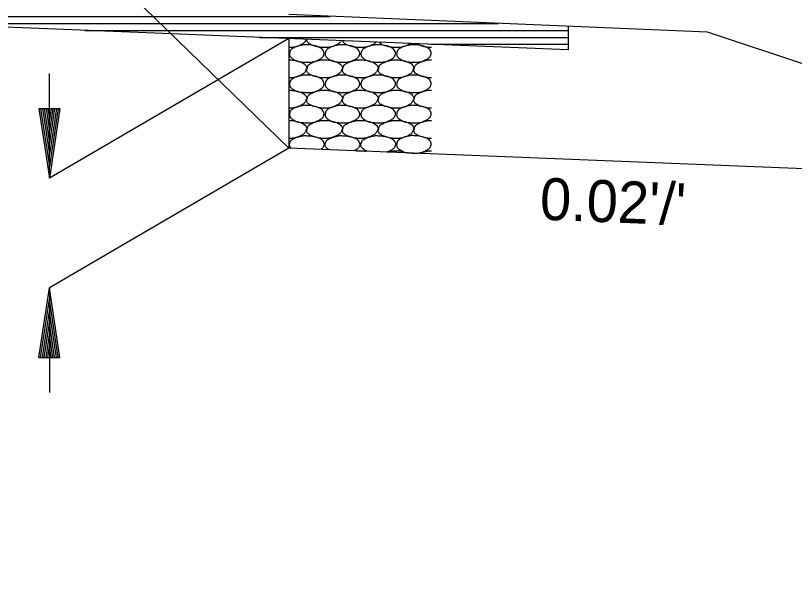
# Model space of a CAD drawing. Extents: x 1955768 to 1955917, y 566446 to 566546.
# Drawn here: x 1955847.75 to 1955858.92, y 566511.42 to 566519.66 of the extents above; entities that cross this region are included whole.
import ezdxf

# ---------------------------------------------------------------- set-up
doc = ezdxf.new("R2010")
doc.units = 0
doc.layers.add('R_Border', color=7, linetype='Continuous')
doc.layers.add('R_Grid', color=7, linetype='Continuous')

msp = doc.modelspace()

# ---------------------------------------------------------------- linework, layer by layer
at = {"layer": 'R_Border'}
for p, q in [((1955851.672, 566517.757), (1955848.84, 566520.502)), ((1955851.759, 566519.325), (1955839.673, 566519.808)), ((1955857.672, 566519.421), (1955851.672, 566519.67)), ((1955843.748, 566519.645), (1955852.265, 566519.645)), ((1955846.248, 566519.545), (1955854.675, 566519.545)), ((1955848.748, 566519.445), (1955855.672, 566519.445)), ((1955855.672, 566519.504), (1955855.672, 566519.164)), ((1955851.248, 566519.345), (1955855.672, 566519.345)), ((1955881.672, 566511.422), (1955857.672, 566519.421)), ((1955851.672, 566519.328), (1955848.238, 566517.328)), ((1955851.672, 566519.328), (1955851.672, 566517.757)), ((1955855.672, 566519.164), (1955851.758, 566519.326)), ((1955853.709, 566519.245), (1955855.672, 566519.245)), ((1955851.672, 566517.757), (1955848.238, 566515.757)), ((1955864.162, 566517.258), (1955851.672, 566517.757))]:
    msp.add_line(p, q, dxfattribs=at)
at = {"layer": 'R_Grid'}
for p, q in [((1955848.238, 566517.328), (1955848.238, 566518.828)), ((1955848.088, 566518.328), (1955848.238, 566517.328)), ((1955848.088, 566518.328), (1955848.388, 566518.328)), ((1955848.113, 566518.328), (1955848.238, 566517.495)), ((1955848.139, 566518.328), (1955848.238, 566517.667)), ((1955848.164, 566518.328), (1955848.238, 566517.834)), ((1955848.19, 566518.328), (1955848.238, 566518.003)), ((1955848.215, 566518.328), (1955848.238, 566518.17)), ((1955848.388, 566518.328), (1955848.238, 566517.328)), ((1955848.287, 566518.328), (1955848.238, 566518.003)), ((1955848.338, 566518.328), (1955848.238, 566517.667)), ((1955848.363, 566518.328), (1955848.238, 566517.495)), ((1955848.313, 566518.328), (1955848.238, 566517.834)), ((1955848.262, 566518.328), (1955848.238, 566518.17)), ((1955848.088, 566514.757), (1955848.238, 566515.757)), ((1955848.238, 566515.757), (1955848.238, 566514.257)), ((1955848.388, 566514.757), (1955848.238, 566515.757)), ((1955848.113, 566514.757), (1955848.238, 566515.59)), ((1955848.363, 566514.757), (1955848.238, 566515.59)), ((1955848.139, 566514.757), (1955848.238, 566515.418)), ((1955848.338, 566514.757), (1955848.238, 566515.418)), ((1955848.164, 566514.757), (1955848.238, 566515.252)), ((1955848.313, 566514.757), (1955848.238, 566515.252)), ((1955848.19, 566514.757), (1955848.238, 566515.082)), ((1955848.287, 566514.757), (1955848.238, 566515.082)), ((1955848.215, 566514.757), (1955848.238, 566514.915)), ((1955848.262, 566514.757), (1955848.238, 566514.915)), ((1955848.088, 566514.757), (1955848.388, 566514.757))]:
    msp.add_line(p, q, dxfattribs=at)
for points in [[(1955851.916, 566519.318), (1955851.914, 566519.3), (1955851.893, 566519.269), (1955851.849, 566519.238), (1955851.79, 566519.213), (1955851.727, 566519.198), (1955851.685, 566519.198), (1955851.672, 566519.198)], [(1955851.928, 566519.238), (1955851.958, 566519.239), (1955852.025, 566519.23), (1955852.118, 566519.204), (1955852.169, 566519.158), (1955852.18, 566519.103), (1955852.156, 566519.059), (1955852.111, 566519.028), (1955852.052, 566519.003), (1955851.987, 566518.987), (1955851.921, 566518.988), (1955851.86, 566518.993), (1955851.791, 566518.998), (1955851.731, 566519.034), (1955851.682, 566519.066), (1955851.677, 566519.117), (1955851.693, 566519.168), (1955851.732, 566519.192), (1955851.78, 566519.213), (1955851.827, 566519.227), (1955851.878, 566519.239), (1955851.91, 566519.24), (1955851.928, 566519.238)], [(1955852.184, 566519.198), (1955852.182, 566519.198), (1955852.157, 566519.198), (1955852.108, 566519.202), (1955852.044, 566519.22), (1955851.979, 566519.238), (1955851.935, 566519.276), (1955851.927, 566519.308), (1955851.926, 566519.318)], [(1955852.422, 566519.298), (1955852.416, 566519.287), (1955852.4, 566519.265), (1955852.361, 566519.238), (1955852.302, 566519.213), (1955852.239, 566519.198), (1955852.197, 566519.198), (1955852.184, 566519.198)], [(1955852.44, 566519.238), (1955852.47, 566519.239), (1955852.537, 566519.23), (1955852.63, 566519.204), (1955852.681, 566519.158), (1955852.692, 566519.103), (1955852.668, 566519.059), (1955852.623, 566519.028), (1955852.564, 566519.003), (1955852.499, 566518.987), (1955852.433, 566518.988), (1955852.372, 566518.993), (1955852.303, 566518.998), (1955852.243, 566519.034), (1955852.194, 566519.066), (1955852.189, 566519.117), (1955852.205, 566519.168), (1955852.244, 566519.192), (1955852.292, 566519.213), (1955852.339, 566519.227), (1955852.39, 566519.239), (1955852.422, 566519.24), (1955852.44, 566519.238)], [(1955852.696, 566519.198), (1955852.694, 566519.198), (1955852.669, 566519.198), (1955852.62, 566519.202), (1955852.556, 566519.22), (1955852.491, 566519.238), (1955852.454, 566519.269), (1955852.444, 566519.294), (1955852.443, 566519.297)], [(1955852.92, 566519.277), (1955852.918, 566519.274), (1955852.906, 566519.26), (1955852.873, 566519.238), (1955852.814, 566519.213), (1955852.751, 566519.198), (1955852.709, 566519.198), (1955852.696, 566519.198)], [(1955852.952, 566519.238), (1955852.982, 566519.239), (1955853.049, 566519.23), (1955853.142, 566519.204), (1955853.193, 566519.158), (1955853.204, 566519.103), (1955853.18, 566519.059), (1955853.135, 566519.028), (1955853.076, 566519.003), (1955853.011, 566518.987), (1955852.945, 566518.988), (1955852.884, 566518.993), (1955852.815, 566518.998), (1955852.755, 566519.034), (1955852.706, 566519.066), (1955852.701, 566519.117), (1955852.717, 566519.168), (1955852.756, 566519.192), (1955852.804, 566519.213), (1955852.851, 566519.227), (1955852.902, 566519.239), (1955852.934, 566519.24), (1955852.952, 566519.238)], [(1955853.208, 566519.198), (1955853.206, 566519.198), (1955853.181, 566519.198), (1955853.132, 566519.202), (1955853.068, 566519.22), (1955853.008, 566519.237), (1955852.977, 566519.261), (1955852.966, 566519.276)], [(1955853.413, 566519.257), (1955853.407, 566519.252), (1955853.381, 566519.236), (1955853.326, 566519.213), (1955853.263, 566519.198), (1955853.221, 566519.198), (1955853.208, 566519.198)], [(1955853.464, 566519.238), (1955853.494, 566519.239), (1955853.561, 566519.23), (1955853.654, 566519.204), (1955853.705, 566519.158), (1955853.716, 566519.103), (1955853.692, 566519.059), (1955853.647, 566519.028), (1955853.588, 566519.003), (1955853.523, 566518.987), (1955853.457, 566518.988), (1955853.396, 566518.993), (1955853.327, 566518.998), (1955853.267, 566519.034), (1955853.218, 566519.066), (1955853.213, 566519.117), (1955853.229, 566519.168), (1955853.268, 566519.192), (1955853.316, 566519.213), (1955853.363, 566519.227), (1955853.414, 566519.239), (1955853.446, 566519.24), (1955853.464, 566519.238)], [(1955853.715, 566519.198), (1955853.714, 566519.198), (1955853.691, 566519.198), (1955853.644, 566519.202), (1955853.58, 566519.22), (1955853.531, 566519.235), (1955853.506, 566519.249), (1955853.5, 566519.254)], [(1955851.672, 566519.022), (1955851.674, 566519.022), (1955851.676, 566519.022), (1955851.678, 566519.022)], [(1955851.678, 566519.022), (1955851.708, 566519.023), (1955851.775, 566519.014), (1955851.864, 566518.988), (1955851.921, 566518.94), (1955851.927, 566518.906), (1955851.928, 566518.895), (1955851.928, 566518.894)], [(1955851.934, 566518.894), (1955851.934, 566518.895), (1955851.935, 566518.912), (1955851.948, 566518.951), (1955851.988, 566518.976), (1955852.036, 566518.997), (1955852.083, 566519.011), (1955852.134, 566519.023), (1955852.166, 566519.024), (1955852.184, 566519.022)], [(1955852.184, 566519.022), (1955852.186, 566519.022), (1955852.188, 566519.022), (1955852.19, 566519.022)], [(1955852.19, 566519.022), (1955852.22, 566519.023), (1955852.287, 566519.014), (1955852.376, 566518.988), (1955852.433, 566518.94), (1955852.439, 566518.906), (1955852.44, 566518.895), (1955852.44, 566518.894)], [(1955852.446, 566518.894), (1955852.446, 566518.895), (1955852.447, 566518.912), (1955852.46, 566518.951), (1955852.5, 566518.976), (1955852.548, 566518.997), (1955852.595, 566519.011), (1955852.646, 566519.023), (1955852.678, 566519.024), (1955852.696, 566519.022)], [(1955852.696, 566519.022), (1955852.698, 566519.022), (1955852.7, 566519.022), (1955852.702, 566519.022)], [(1955852.702, 566519.022), (1955852.732, 566519.023), (1955852.799, 566519.014), (1955852.888, 566518.988), (1955852.945, 566518.94), (1955852.951, 566518.906), (1955852.952, 566518.895), (1955852.952, 566518.894)], [(1955852.958, 566518.894), (1955852.958, 566518.895), (1955852.959, 566518.912), (1955852.972, 566518.951), (1955853.012, 566518.976), (1955853.06, 566518.997), (1955853.107, 566519.011), (1955853.158, 566519.023), (1955853.19, 566519.024), (1955853.208, 566519.022)], [(1955853.208, 566519.022), (1955853.21, 566519.022), (1955853.212, 566519.022), (1955853.214, 566519.022)], [(1955853.214, 566519.022), (1955853.244, 566519.023), (1955853.311, 566519.014), (1955853.4, 566518.988), (1955853.457, 566518.94), (1955853.463, 566518.906), (1955853.464, 566518.895), (1955853.464, 566518.894)], [(1955853.47, 566518.894), (1955853.47, 566518.895), (1955853.471, 566518.912), (1955853.484, 566518.951), (1955853.524, 566518.976), (1955853.572, 566518.997), (1955853.619, 566519.011), (1955853.668, 566519.022), (1955853.698, 566519.024), (1955853.715, 566519.023)], [(1955851.916, 566518.894), (1955851.916, 566518.892), (1955851.917, 566518.87), (1955851.894, 566518.836), (1955851.849, 566518.804), (1955851.79, 566518.779), (1955851.727, 566518.764), (1955851.685, 566518.764), (1955851.672, 566518.764)], [(1955852.184, 566518.764), (1955852.182, 566518.764), (1955852.157, 566518.764), (1955852.108, 566518.768), (1955852.044, 566518.786), (1955851.979, 566518.804), (1955851.933, 566518.843), (1955851.926, 566518.879), (1955851.926, 566518.892), (1955851.926, 566518.894)], [(1955852.428, 566518.894), (1955852.428, 566518.892), (1955852.429, 566518.87), (1955852.406, 566518.836), (1955852.361, 566518.804), (1955852.302, 566518.779), (1955852.239, 566518.764), (1955852.197, 566518.764), (1955852.184, 566518.764)], [(1955852.696, 566518.764), (1955852.694, 566518.764), (1955852.669, 566518.764), (1955852.62, 566518.768), (1955852.556, 566518.786), (1955852.491, 566518.804), (1955852.445, 566518.843), (1955852.438, 566518.879), (1955852.438, 566518.892), (1955852.438, 566518.894)], [(1955852.94, 566518.894), (1955852.94, 566518.892), (1955852.941, 566518.87), (1955852.918, 566518.836), (1955852.873, 566518.804), (1955852.814, 566518.779), (1955852.751, 566518.764), (1955852.709, 566518.764), (1955852.696, 566518.764)], [(1955853.208, 566518.764), (1955853.206, 566518.764), (1955853.181, 566518.764), (1955853.132, 566518.768), (1955853.068, 566518.786), (1955853.003, 566518.804), (1955852.957, 566518.843), (1955852.95, 566518.879), (1955852.95, 566518.892), (1955852.95, 566518.894)], [(1955853.452, 566518.894), (1955853.452, 566518.892), (1955853.453, 566518.87), (1955853.43, 566518.836), (1955853.385, 566518.804), (1955853.326, 566518.779), (1955853.263, 566518.764), (1955853.221, 566518.764), (1955853.208, 566518.764)], [(1955853.715, 566518.764), (1955853.714, 566518.764), (1955853.691, 566518.764), (1955853.644, 566518.768), (1955853.58, 566518.786), (1955853.515, 566518.804), (1955853.469, 566518.843), (1955853.462, 566518.879), (1955853.462, 566518.892), (1955853.462, 566518.894)], [(1955851.928, 566518.804), (1955851.958, 566518.805), (1955852.025, 566518.796), (1955852.118, 566518.77), (1955852.169, 566518.724), (1955852.18, 566518.669), (1955852.156, 566518.625), (1955852.111, 566518.594), (1955852.052, 566518.569), (1955851.987, 566518.553), (1955851.921, 566518.554), (1955851.86, 566518.559), (1955851.791, 566518.564), (1955851.731, 566518.6), (1955851.682, 566518.632), (1955851.677, 566518.683), (1955851.693, 566518.734), (1955851.732, 566518.758), (1955851.78, 566518.779), (1955851.827, 566518.793), (1955851.878, 566518.805), (1955851.91, 566518.806), (1955851.928, 566518.804)], [(1955852.44, 566518.804), (1955852.47, 566518.805), (1955852.537, 566518.796), (1955852.63, 566518.77), (1955852.681, 566518.724), (1955852.692, 566518.669), (1955852.668, 566518.625), (1955852.623, 566518.594), (1955852.564, 566518.569), (1955852.499, 566518.553), (1955852.433, 566518.554), (1955852.372, 566518.559), (1955852.303, 566518.564), (1955852.243, 566518.6), (1955852.194, 566518.632), (1955852.189, 566518.683), (1955852.205, 566518.734), (1955852.244, 566518.758), (1955852.292, 566518.779), (1955852.339, 566518.793), (1955852.39, 566518.805), (1955852.422, 566518.806), (1955852.44, 566518.804)], [(1955852.952, 566518.804), (1955852.982, 566518.805), (1955853.049, 566518.796), (1955853.142, 566518.77), (1955853.193, 566518.724), (1955853.204, 566518.669), (1955853.18, 566518.625), (1955853.135, 566518.594), (1955853.076, 566518.569), (1955853.011, 566518.553), (1955852.945, 566518.554), (1955852.884, 566518.559), (1955852.815, 566518.564), (1955852.755, 566518.6), (1955852.706, 566518.632), (1955852.701, 566518.683), (1955852.717, 566518.734), (1955852.756, 566518.758), (1955852.804, 566518.779), (1955852.851, 566518.793), (1955852.902, 566518.805), (1955852.934, 566518.806), (1955852.952, 566518.804)], [(1955853.464, 566518.804), (1955853.494, 566518.805), (1955853.561, 566518.796), (1955853.654, 566518.77), (1955853.705, 566518.724), (1955853.716, 566518.669), (1955853.692, 566518.625), (1955853.647, 566518.594), (1955853.588, 566518.569), (1955853.523, 566518.553), (1955853.457, 566518.554), (1955853.396, 566518.559), (1955853.327, 566518.564), (1955853.267, 566518.6), (1955853.218, 566518.632), (1955853.213, 566518.683), (1955853.229, 566518.734), (1955853.268, 566518.758), (1955853.316, 566518.779), (1955853.363, 566518.793), (1955853.414, 566518.805), (1955853.446, 566518.806), (1955853.464, 566518.804)], [(1955851.672, 566518.588), (1955851.674, 566518.588), (1955851.676, 566518.588), (1955851.678, 566518.588)], [(1955851.678, 566518.588), (1955851.708, 566518.589), (1955851.775, 566518.58), (1955851.864, 566518.554), (1955851.921, 566518.506), (1955851.927, 566518.472), (1955851.928, 566518.461), (1955851.928, 566518.46)], [(1955851.934, 566518.46), (1955851.934, 566518.461), (1955851.935, 566518.478), (1955851.948, 566518.517), (1955851.988, 566518.542), (1955852.036, 566518.563), (1955852.083, 566518.577), (1955852.134, 566518.589), (1955852.166, 566518.59), (1955852.184, 566518.588)], [(1955852.184, 566518.588), (1955852.186, 566518.588), (1955852.188, 566518.588), (1955852.19, 566518.588)], [(1955852.19, 566518.588), (1955852.22, 566518.589), (1955852.287, 566518.58), (1955852.376, 566518.554), (1955852.433, 566518.506), (1955852.439, 566518.472), (1955852.44, 566518.461), (1955852.44, 566518.46)], [(1955852.446, 566518.46), (1955852.446, 566518.461), (1955852.447, 566518.478), (1955852.46, 566518.517), (1955852.5, 566518.542), (1955852.548, 566518.563), (1955852.595, 566518.577), (1955852.646, 566518.589), (1955852.678, 566518.59), (1955852.696, 566518.588)], [(1955852.696, 566518.588), (1955852.698, 566518.588), (1955852.7, 566518.588), (1955852.702, 566518.588)], [(1955852.702, 566518.588), (1955852.732, 566518.589), (1955852.799, 566518.58), (1955852.888, 566518.554), (1955852.945, 566518.506), (1955852.951, 566518.472), (1955852.952, 566518.461), (1955852.952, 566518.46)], [(1955852.958, 566518.46), (1955852.958, 566518.461), (1955852.959, 566518.478), (1955852.972, 566518.517), (1955853.012, 566518.542), (1955853.06, 566518.563), (1955853.107, 566518.577), (1955853.158, 566518.589), (1955853.19, 566518.59), (1955853.208, 566518.588)], [(1955853.208, 566518.588), (1955853.21, 566518.588), (1955853.212, 566518.588), (1955853.214, 566518.588)], [(1955853.214, 566518.588), (1955853.244, 566518.589), (1955853.311, 566518.58), (1955853.4, 566518.554), (1955853.457, 566518.506), (1955853.463, 566518.472), (1955853.464, 566518.461), (1955853.464, 566518.46)], [(1955853.47, 566518.46), (1955853.47, 566518.461), (1955853.471, 566518.478), (1955853.484, 566518.517), (1955853.524, 566518.542), (1955853.572, 566518.563), (1955853.619, 566518.577), (1955853.668, 566518.588), (1955853.698, 566518.59), (1955853.715, 566518.589)], [(1955851.916, 566518.46), (1955851.916, 566518.458), (1955851.917, 566518.436), (1955851.894, 566518.402), (1955851.849, 566518.37), (1955851.79, 566518.345), (1955851.727, 566518.33), (1955851.685, 566518.33), (1955851.672, 566518.33)], [(1955852.184, 566518.33), (1955852.182, 566518.33), (1955852.157, 566518.33), (1955852.108, 566518.334), (1955852.044, 566518.352), (1955851.979, 566518.37), (1955851.933, 566518.409), (1955851.926, 566518.445), (1955851.926, 566518.458), (1955851.926, 566518.46)], [(1955852.428, 566518.46), (1955852.428, 566518.458), (1955852.429, 566518.436), (1955852.406, 566518.402), (1955852.361, 566518.37), (1955852.302, 566518.345), (1955852.239, 566518.33), (1955852.197, 566518.33), (1955852.184, 566518.33)], [(1955852.696, 566518.33), (1955852.694, 566518.33), (1955852.669, 566518.33), (1955852.62, 566518.334), (1955852.556, 566518.352), (1955852.491, 566518.37), (1955852.445, 566518.409), (1955852.438, 566518.445), (1955852.438, 566518.458), (1955852.438, 566518.46)], [(1955852.94, 566518.46), (1955852.94, 566518.458), (1955852.941, 566518.436), (1955852.918, 566518.402), (1955852.873, 566518.37), (1955852.814, 566518.345), (1955852.751, 566518.33), (1955852.709, 566518.33), (1955852.696, 566518.33)], [(1955853.208, 566518.33), (1955853.206, 566518.33), (1955853.181, 566518.33), (1955853.132, 566518.334), (1955853.068, 566518.352), (1955853.003, 566518.37), (1955852.957, 566518.409), (1955852.95, 566518.445), (1955852.95, 566518.458), (1955852.95, 566518.46)], [(1955853.452, 566518.46), (1955853.452, 566518.458), (1955853.453, 566518.436), (1955853.43, 566518.402), (1955853.385, 566518.37), (1955853.326, 566518.345), (1955853.263, 566518.33), (1955853.221, 566518.33), (1955853.208, 566518.33)], [(1955853.715, 566518.33), (1955853.714, 566518.33), (1955853.691, 566518.33), (1955853.644, 566518.334), (1955853.58, 566518.352), (1955853.515, 566518.37), (1955853.469, 566518.409), (1955853.462, 566518.445), (1955853.462, 566518.458), (1955853.462, 566518.46)], [(1955851.928, 566518.37), (1955851.958, 566518.371), (1955852.025, 566518.362), (1955852.118, 566518.336), (1955852.169, 566518.29), (1955852.18, 566518.235), (1955852.156, 566518.191), (1955852.111, 566518.16), (1955852.052, 566518.135), (1955851.987, 566518.119), (1955851.921, 566518.12), (1955851.86, 566518.125), (1955851.791, 566518.13), (1955851.731, 566518.166), (1955851.682, 566518.198), (1955851.677, 566518.249), (1955851.693, 566518.3), (1955851.732, 566518.324), (1955851.78, 566518.345), (1955851.827, 566518.359), (1955851.878, 566518.371), (1955851.91, 566518.372), (1955851.928, 566518.37)], [(1955852.44, 566518.37), (1955852.47, 566518.371), (1955852.537, 566518.362), (1955852.63, 566518.336), (1955852.681, 566518.29), (1955852.692, 566518.235), (1955852.668, 566518.191), (1955852.623, 566518.16), (1955852.564, 566518.135), (1955852.499, 566518.119), (1955852.433, 566518.12), (1955852.372, 566518.125), (1955852.303, 566518.13), (1955852.243, 566518.166), (1955852.194, 566518.198), (1955852.189, 566518.249), (1955852.205, 566518.3), (1955852.244, 566518.324), (1955852.292, 566518.345), (1955852.339, 566518.359), (1955852.39, 566518.371), (1955852.422, 566518.372), (1955852.44, 566518.37)], [(1955852.952, 566518.37), (1955852.982, 566518.371), (1955853.049, 566518.362), (1955853.142, 566518.336), (1955853.193, 566518.29), (1955853.204, 566518.235), (1955853.18, 566518.191), (1955853.135, 566518.16), (1955853.076, 566518.135), (1955853.011, 566518.119), (1955852.945, 566518.12), (1955852.884, 566518.125), (1955852.815, 566518.13), (1955852.755, 566518.166), (1955852.706, 566518.198), (1955852.701, 566518.249), (1955852.717, 566518.3), (1955852.756, 566518.324), (1955852.804, 566518.345), (1955852.851, 566518.359), (1955852.902, 566518.371), (1955852.934, 566518.372), (1955852.952, 566518.37)], [(1955853.464, 566518.37), (1955853.494, 566518.371), (1955853.561, 566518.362), (1955853.654, 566518.336), (1955853.705, 566518.29), (1955853.716, 566518.235), (1955853.692, 566518.191), (1955853.647, 566518.16), (1955853.588, 566518.135), (1955853.523, 566518.119), (1955853.457, 566518.12), (1955853.396, 566518.125), (1955853.327, 566518.13), (1955853.267, 566518.166), (1955853.218, 566518.198), (1955853.213, 566518.249), (1955853.229, 566518.3), (1955853.268, 566518.324), (1955853.316, 566518.345), (1955853.363, 566518.359), (1955853.414, 566518.371), (1955853.446, 566518.372), (1955853.464, 566518.37)], [(1955851.672, 566518.154), (1955851.674, 566518.154), (1955851.676, 566518.154), (1955851.678, 566518.154)], [(1955851.678, 566518.154), (1955851.708, 566518.155), (1955851.775, 566518.146), (1955851.864, 566518.12), (1955851.921, 566518.072), (1955851.927, 566518.038), (1955851.928, 566518.027), (1955851.928, 566518.026)], [(1955851.934, 566518.026), (1955851.934, 566518.027), (1955851.935, 566518.044), (1955851.948, 566518.083), (1955851.988, 566518.108), (1955852.036, 566518.129), (1955852.083, 566518.143), (1955852.134, 566518.155), (1955852.166, 566518.156), (1955852.184, 566518.154)], [(1955852.184, 566518.154), (1955852.186, 566518.154), (1955852.188, 566518.154), (1955852.19, 566518.154)], [(1955852.19, 566518.154), (1955852.22, 566518.155), (1955852.287, 566518.146), (1955852.376, 566518.12), (1955852.433, 566518.072), (1955852.439, 566518.038), (1955852.44, 566518.027), (1955852.44, 566518.026)], [(1955852.446, 566518.026), (1955852.446, 566518.027), (1955852.447, 566518.044), (1955852.46, 566518.083), (1955852.5, 566518.108), (1955852.548, 566518.129), (1955852.595, 566518.143), (1955852.646, 566518.155), (1955852.678, 566518.156), (1955852.696, 566518.154)], [(1955852.696, 566518.154), (1955852.698, 566518.154), (1955852.7, 566518.154), (1955852.702, 566518.154)], [(1955852.702, 566518.154), (1955852.732, 566518.155), (1955852.799, 566518.146), (1955852.888, 566518.12), (1955852.945, 566518.072), (1955852.951, 566518.038), (1955852.952, 566518.027), (1955852.952, 566518.026)], [(1955852.958, 566518.026), (1955852.958, 566518.027), (1955852.959, 566518.044), (1955852.972, 566518.083), (1955853.012, 566518.108), (1955853.06, 566518.129), (1955853.107, 566518.143), (1955853.158, 566518.155), (1955853.19, 566518.156), (1955853.208, 566518.154)], [(1955853.208, 566518.154), (1955853.21, 566518.154), (1955853.212, 566518.154), (1955853.214, 566518.154)], [(1955853.214, 566518.154), (1955853.244, 566518.155), (1955853.311, 566518.146), (1955853.4, 566518.12), (1955853.457, 566518.072), (1955853.463, 566518.038), (1955853.464, 566518.027), (1955853.464, 566518.026)], [(1955853.47, 566518.026), (1955853.47, 566518.027), (1955853.471, 566518.044), (1955853.484, 566518.083), (1955853.524, 566518.108), (1955853.572, 566518.129), (1955853.619, 566518.143), (1955853.668, 566518.154), (1955853.698, 566518.156), (1955853.715, 566518.155)], [(1955851.916, 566518.026), (1955851.916, 566518.024), (1955851.917, 566518.002), (1955851.894, 566517.968), (1955851.849, 566517.936), (1955851.79, 566517.911), (1955851.727, 566517.896), (1955851.685, 566517.896), (1955851.672, 566517.896)], [(1955852.184, 566517.896), (1955852.182, 566517.896), (1955852.157, 566517.896), (1955852.108, 566517.9), (1955852.044, 566517.918), (1955851.979, 566517.936), (1955851.933, 566517.975), (1955851.926, 566518.011), (1955851.926, 566518.024), (1955851.926, 566518.026)], [(1955852.428, 566518.026), (1955852.428, 566518.024), (1955852.429, 566518.002), (1955852.406, 566517.968), (1955852.361, 566517.936), (1955852.302, 566517.911), (1955852.239, 566517.896), (1955852.197, 566517.896), (1955852.184, 566517.896)], [(1955852.696, 566517.896), (1955852.694, 566517.896), (1955852.669, 566517.896), (1955852.62, 566517.9), (1955852.556, 566517.918), (1955852.491, 566517.936), (1955852.445, 566517.975), (1955852.438, 566518.011), (1955852.438, 566518.024), (1955852.438, 566518.026)], [(1955852.94, 566518.026), (1955852.94, 566518.024), (1955852.941, 566518.002), (1955852.918, 566517.968), (1955852.873, 566517.936), (1955852.814, 566517.911), (1955852.751, 566517.896), (1955852.709, 566517.896), (1955852.696, 566517.896)], [(1955853.208, 566517.896), (1955853.206, 566517.896), (1955853.181, 566517.896), (1955853.132, 566517.9), (1955853.068, 566517.918), (1955853.003, 566517.936), (1955852.957, 566517.975), (1955852.95, 566518.011), (1955852.95, 566518.024), (1955852.95, 566518.026)], [(1955853.452, 566518.026), (1955853.452, 566518.024), (1955853.453, 566518.002), (1955853.43, 566517.968), (1955853.385, 566517.936), (1955853.326, 566517.911), (1955853.263, 566517.896), (1955853.221, 566517.896), (1955853.208, 566517.896)], [(1955853.715, 566517.896), (1955853.714, 566517.896), (1955853.691, 566517.896), (1955853.644, 566517.9), (1955853.58, 566517.918), (1955853.515, 566517.936), (1955853.469, 566517.975), (1955853.462, 566518.011), (1955853.462, 566518.024), (1955853.462, 566518.026)], [(1955851.703, 566517.756), (1955851.697, 566517.762), (1955851.68, 566517.779), (1955851.677, 566517.815), (1955851.693, 566517.866), (1955851.732, 566517.89), (1955851.78, 566517.911), (1955851.827, 566517.925), (1955851.878, 566517.937), (1955851.91, 566517.938), (1955851.928, 566517.936)], [(1955851.928, 566517.936), (1955851.958, 566517.937), (1955852.025, 566517.928), (1955852.118, 566517.902), (1955852.169, 566517.856), (1955852.18, 566517.801), (1955852.159, 566517.762), (1955852.138, 566517.744), (1955852.131, 566517.739)], [(1955852.242, 566517.735), (1955852.225, 566517.746), (1955852.194, 566517.767), (1955852.189, 566517.815), (1955852.205, 566517.866), (1955852.244, 566517.89), (1955852.292, 566517.911), (1955852.339, 566517.925), (1955852.39, 566517.937), (1955852.422, 566517.938), (1955852.44, 566517.936)], [(1955852.44, 566517.936), (1955852.47, 566517.937), (1955852.537, 566517.928), (1955852.63, 566517.902), (1955852.681, 566517.856), (1955852.692, 566517.801), (1955852.668, 566517.757), (1955852.636, 566517.734), (1955852.617, 566517.724), (1955852.609, 566517.72)], [(1955852.791, 566517.713), (1955852.781, 566517.718), (1955852.749, 566517.736), (1955852.706, 566517.764), (1955852.701, 566517.815), (1955852.717, 566517.866), (1955852.756, 566517.89), (1955852.804, 566517.911), (1955852.851, 566517.925), (1955852.902, 566517.937), (1955852.934, 566517.938), (1955852.952, 566517.936)], [(1955852.952, 566517.936), (1955852.982, 566517.937), (1955853.049, 566517.928), (1955853.142, 566517.902), (1955853.193, 566517.856), (1955853.204, 566517.801), (1955853.18, 566517.757), (1955853.135, 566517.726), (1955853.101, 566517.71), (1955853.076, 566517.702), (1955853.073, 566517.701)], [(1955853.464, 566517.936), (1955853.494, 566517.937), (1955853.561, 566517.928), (1955853.654, 566517.902), (1955853.705, 566517.856), (1955853.716, 566517.801), (1955853.692, 566517.757), (1955853.647, 566517.726), (1955853.588, 566517.701), (1955853.523, 566517.685), (1955853.457, 566517.686), (1955853.396, 566517.691), (1955853.327, 566517.696), (1955853.267, 566517.732), (1955853.218, 566517.764), (1955853.213, 566517.815), (1955853.229, 566517.866), (1955853.268, 566517.89), (1955853.316, 566517.911), (1955853.363, 566517.925), (1955853.414, 566517.937), (1955853.446, 566517.938), (1955853.464, 566517.936)], [(1955852.642, 566517.719), (1955852.66, 566517.721), (1955852.678, 566517.722), (1955852.696, 566517.72)], [(1955852.696, 566517.72), (1955852.698, 566517.72), (1955852.7, 566517.72), (1955852.702, 566517.72)], [(1955852.702, 566517.72), (1955852.726, 566517.721), (1955852.751, 566517.718), (1955852.775, 566517.713)], [(1955853.082, 566517.701), (1955853.092, 566517.704), (1955853.116, 566517.711), (1955853.158, 566517.721), (1955853.19, 566517.722), (1955853.208, 566517.72)], [(1955853.208, 566517.72), (1955853.21, 566517.72), (1955853.212, 566517.72), (1955853.214, 566517.72)], [(1955853.214, 566517.72), (1955853.244, 566517.721), (1955853.299, 566517.713), (1955853.35, 566517.699), (1955853.372, 566517.689)], [(1955853.543, 566517.683), (1955853.55, 566517.686), (1955853.578, 566517.697), (1955853.619, 566517.709), (1955853.668, 566517.72), (1955853.698, 566517.722), (1955853.715, 566517.721)]]:
    msp.add_open_spline(points, degree=3, dxfattribs=at)

# ---------------------------------------------------------------- texts
at = {"layer": 'R_Border'}
msp.add_text("0.02'/'", height=0.6, rotation=357.7094, dxfattribs=at).set_placement((1955855.261, 566516.735))

doc.saveas('drawing.dxf')
